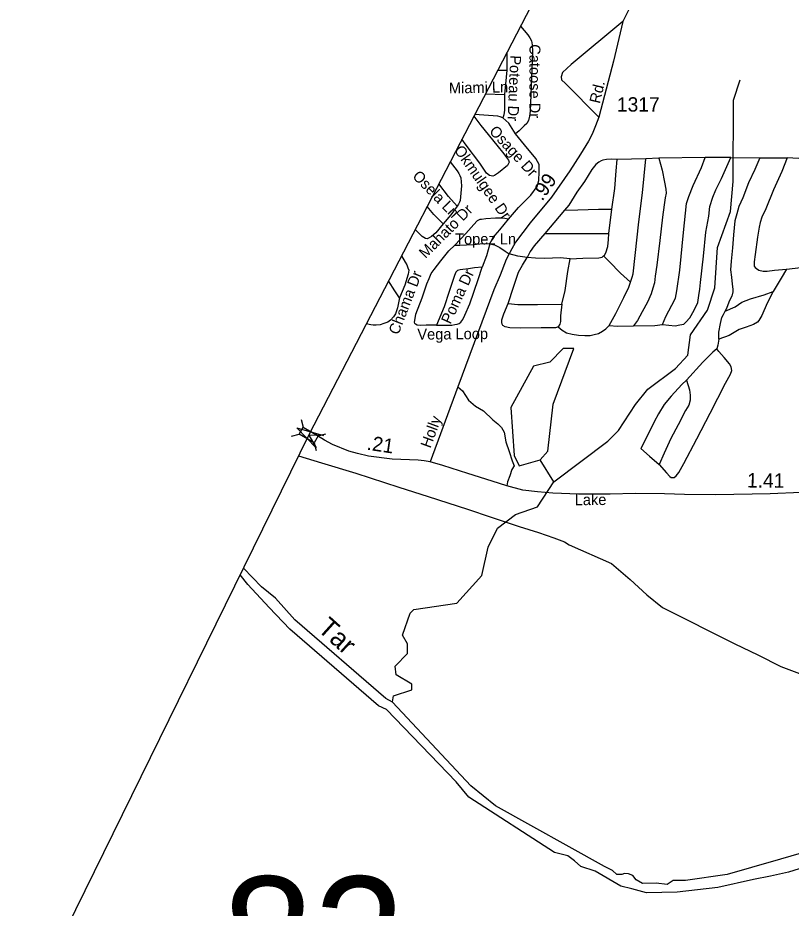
# Model space of a CAD drawing. Extents: x 2220236 to 2384410, y 720751 to 894131.
# Drawn here: x 2239554 to 2246280, y 793475 to 801219 of the extents above; entities that cross this region are included whole.
import ezdxf

# ---------------------------------------------------------------- set-up
doc = ezdxf.new("R2010")
doc.units = 0
for name, color, linetype in [('Exist Boundary Political CountyLine', 7, 'Continuous'), ('Exist Hydrographic Misc Water Feature', 7, 'Continuous'), ('Exist Hydrographic Pond Under 1500 Sq Ft', 7, 'Continuous'), ('Exist Hydrographic River Shore', 7, 'Continuous'), ('Exist Hydrographic River Shore Label', 7, 'Continuous'), ('Exist Railroad Mainline', 7, 'Continuous'), ('Exist Road Non-System Type 51', 7, 'Continuous'), ('Exist Road Non-System Type 51 Label', 7, 'Continuous'), ('Exist Road Secondary Mileage Hundredths English Label', 7, 'Continuous'), ('Exist Road Secondary Structure Standard Bridge Attributed CELL', 7, 'Continuous'), ('Exist Road Secondary Structure Standard Bridge CELL', 7, 'Continuous'), ('Exist Road Secondary Structure Standard Bridge Number Label', 7, 'Continuous'), ('Exist Road Secondary Type 51 Attributed', 7, 'Continuous'), ('Exist Road Secondary Type 51 Label', 7, 'Continuous'), ('Exist Road Secondary Type 51 Number Label', 7, 'Continuous')]:
    doc.layers.add(name, color=color, linetype=linetype)

msp = doc.modelspace()

# ---------------------------------------------------------------- linework, layer by layer
at = {"layer": 'Exist Boundary Political CountyLine'}
msp.add_lwpolyline([(2293117.8, 894131.3), (2291903.9, 891776.4), (2258821.6, 829664.6), (2255410.5, 823324), (2242088.6, 797598.7), (2231459.6, 775980.5), (2225010.8, 762953.2), (2220575.6, 753519.5)], dxfattribs=at)
at = {"layer": 'Exist Hydrographic Misc Water Feature'}
msp.add_line((2244214.5, 797182.9), (2244096.6, 797375.5), dxfattribs=at)
for points in [[(2244214.5, 797182.9), (2244686.6, 797537.2), (2244777.6, 797630.4), (2244925.7, 797857), (2245032.7, 797989.3), (2245272.6, 798168), (2245380.7, 798283.8), (2245403.6, 798460.5), (2245551.7, 798677.2), (2245616.7, 798869.4), (2245639.7, 799219.9), (2245752.7, 799535.7), (2245775.6, 799794.4), (2245778.7, 800502.8), (2245835.7, 800678.7)], [(2242812.8, 795268.5), (2242821.6, 795322.3), (2242979.7, 795374.8), (2242979.7, 795423.9), (2242845.6, 795505.4), (2242836.6, 795581), (2242943.6, 795690.4), (2242943.6, 795775.6), (2242900.5, 795848.7), (2242966.6, 796040.9), (2242999.6, 796073), (2243373.6, 796127.6), (2243588.7, 796369.2), (2243644.7, 796614), (2243726.7, 796779.6), (2243883.6, 796897.7), (2244074.7, 796966), (2244214.5, 797182.9)]]:
    msp.add_lwpolyline(points, dxfattribs=at)
at = {"layer": 'Exist Hydrographic Pond Under 1500 Sq Ft'}
msp.add_lwpolyline([(2244096.6, 797375.5), (2244162.7, 797449.6), (2244209.6, 797858.6), (2244388.6, 798343.7), (2244296.6, 798342.3), (2244181.7, 798223.3), (2244039.6, 798190.1), (2243842.6, 797830.1), (2243871.7, 797413), (2243913.7, 797323.5), (2244096.6, 797375.5)], dxfattribs=at)
at = {"layer": 'Exist Hydrographic River Shore'}
for points in [[(2242813.9, 795268), (2242753.7, 795297.4), (2241964.8, 795982.4), (2241793.9, 796172.1), (2241673.7, 796271.2), (2241515.8, 796433.6)], [(2242761, 795202.9), (2242692.2, 795234.1), (2241918.9, 795901.1), (2241739.7, 796090.8), (2241554.2, 796290.9), (2241486.9, 796374.9)], [(2246457.5, 793979.4), (2246186.6, 793902.1), (2245934.4, 793829.6), (2245721.7, 793768.9), (2245361.1, 793716.8), (2245254.8, 793714.7), (2245200.7, 793681.3), (2245106.9, 793693.8), (2244987, 793689.7), (2244932.8, 793723), (2244903.6, 793760.5), (2244864, 793775.1), (2244830.7, 793777.2), (2244805.7, 793768.9), (2244764, 793766.8), (2244726.5, 793804.3), (2244655.6, 793837.7), (2243709.9, 794365.8), (2243493.9, 794539.6), (2242813.9, 795268)], [(2248133.3, 794333.7), (2247487.2, 794296), (2247206.4, 794232.9), (2246432.5, 793843.9), (2246257.4, 793787.6), (2246100, 793754.3), (2245952, 793725.1), (2245641.5, 793654.2), (2245287.2, 793614.6), (2245020.4, 793608.4), (2244895.3, 793643.8), (2244797.3, 793666.7), (2244576.4, 793796), (2244449.3, 793837.7), (2244395.1, 793885.6), (2244338.8, 793931.5), (2244222.1, 793960.6), (2243475.9, 794442.1), (2243365.4, 794573.4), (2242761, 795202.9)]]:
    msp.add_lwpolyline(points, dxfattribs=at)
at = {"layer": 'Exist Railroad Mainline'}
msp.add_lwpolyline([(2241996.1, 797410.4), (2242194.8, 797349), (2242493.3, 797259.4), (2242868.3, 797136.7), (2243122.7, 797056.7), (2243463.6, 796945.4), (2243671.9, 796877.1), (2243914.6, 796795.2), (2244082.9, 796742.7), (2244215.3, 796695.8), (2244309.6, 796662.4), (2244349.8, 796634.8), (2244716.1, 796474.3), (2244878.6, 796332.6), (2245024.5, 796199.2), (2245162.1, 796090.8), (2245789.5, 795774), (2245989.6, 795678.1), (2246189.7, 795578.1), (2246375.2, 795507.2)], dxfattribs=at)
at = {"layer": 'Exist Road Non-System Type 51'}
for p, q in [((2243728, 800764.5), (2243807.9, 800762.9)), ((2243807.9, 800762.9), (2243787.9, 800552.8)), ((2243621.4, 800558.6), (2243787.9, 800552.8)), ((2245015.6, 799992.7), (2244765.9, 799985.5)), ((2245129.2, 799996.9), (2245015.6, 799992.7)), ((2245531.6, 800005.1), (2245129.2, 799996.9)), ((2245754.5, 800003), (2245531.6, 800005.1)), ((2245754.5, 800003), (2246008.3, 800002)), ((2244693.7, 799342.2), (2244720.5, 799553.9)), ((2246239.5, 799033.5), (2246363.3, 799047.9))]:
    msp.add_line(p, q, dxfattribs=at)
for points in [[(2243925.9, 801146.6), (2243988.5, 801071), (2244008.2, 801044.7), (2244020.1, 801018.4), (2244026.6, 800984.2), (2244029.3, 800924.9), (2244016.1, 800549.9), (2244010.8, 800407.8), (2244003, 800363.1), (2243994.4, 800326.9), (2243979.9, 800300.6), (2243958.9, 800278.2), (2243914.1, 800234.8), (2243881.2, 800211.1)], [(2244815.9, 801186.1), (2244366, 800811.5), (2244291.6, 800743.2), (2244279.2, 800706), (2244281.1, 800681), (2244316.3, 800647.9), (2244606, 800354.1)], [(2243806, 800915), (2243807.7, 800848), (2243807.9, 800762.9)], [(2243787.9, 800552.8), (2243785.8, 800416.2), (2243781.7, 800374.8), (2243773.4, 800350)], [(2243520.3, 800363.3), (2243580.4, 800281.9), (2243719.4, 800112.4), (2243780.5, 800035.7), (2243804.5, 800005.1), (2243822.5, 799979.9), (2243826, 799963.7), (2243812.9, 799935.6), (2243734, 799871.9), (2243698.9, 799847.1), (2243684.5, 799843), (2243655.6, 799847.1), (2243630.8, 799867.8), (2243571.4, 799953.6), (2243453.9, 800112.4), (2243416.7, 800163.3)], [(2243773.4, 800350), (2243749.9, 800359.2), (2243727.8, 800364.6), (2243527.2, 800376.7)], [(2243881.2, 800211.1), (2243824.7, 800303.2), (2243773.4, 800350)], [(2243822.8, 799468.2), (2243909.4, 799570.4), (2244016.8, 799675.6), (2244070.7, 799751.9), (2244084.5, 799803.9), (2244088.5, 799878.9), (2244087.2, 799943.3), (2244074, 799969.7), (2244059.5, 799994.7), (2243960.2, 800113.7), (2243881.2, 800211.1)], [(2243315.5, 799967.8), (2243375.7, 799887.3), (2243389.8, 799864.3), (2243399.4, 799847.5), (2243407.8, 799827.1), (2243412.6, 799758.8), (2243402.7, 799662.6), (2243400, 799630.6), (2243394.6, 799616.2), (2243385.6, 799598.2), (2243374.8, 799582)], [(2244765.9, 799985.5), (2244714.3, 799989.6), (2244673.1, 799985.5), (2244642.1, 799981.4), (2244627.6, 799975.2), (2244607, 799964.8), (2244582.2, 799944.2), (2244545.1, 799898.8), (2244483.2, 799795.5), (2244415.1, 799702.6), (2244344.9, 799589), (2244309.8, 799545.6)], [(2244720.5, 799553.9), (2244747.3, 799734.6), (2244757.7, 799889.5), (2244765.9, 799985.5)], [(2244881.5, 798920.9), (2244897.5, 798964.4), (2244905.7, 798993.4), (2244922.8, 799152.2), (2244953.7, 799445.5), (2244986.8, 799697.4), (2245015.6, 799992.7)], [(2245129.2, 799996.9), (2245158, 799894.6), (2245178.7, 799789.3), (2245191.1, 799729.4), (2245193.1, 799694.3), (2245184.9, 799653), (2245176.6, 799591.1), (2245160.1, 799485.7), (2245137.4, 799283.3), (2245110.6, 799068.6), (2245098.2, 798971.5), (2245089.9, 798912.7), (2245077.6, 798867.2), (2245061, 798819.7), (2245030.1, 798745.4), (2244982.6, 798660.7), (2244943.4, 798586.4), (2244908.3, 798539.9)], [(2245160.1, 798550.2), (2245191.1, 798621.5), (2245240.6, 798718.5), (2245273.6, 798780.5), (2245286, 798844.5), (2245312.8, 799024.2), (2245343.8, 799350.5), (2245370.6, 799604.5), (2245389.2, 799665.4), (2245426.3, 799760.4), (2245498.6, 799917.3), (2245531.6, 800005.1)], [(2245160.1, 798550.2), (2245269.5, 798539.9), (2245310.8, 798548.2), (2245345.9, 798554.4), (2245364.4, 798570.9), (2245399.5, 798610.1), (2245436.7, 798676.2), (2245467.6, 798742.3), (2245477.9, 798804.2), (2245484.1, 798857.9), (2245490.3, 798917.8), (2245517.2, 799145), (2245537.8, 799353.6), (2245562.6, 799494), (2245572.9, 799578.7), (2245597.6, 799658.2), (2245624.5, 799723.2), (2245674, 799821.3), (2245754.5, 800003)], [(2246008.3, 800002), (2245962.9, 799900.8), (2245909.3, 799783.1), (2245859.7, 799653), (2245824.7, 799578.7), (2245806.1, 799514.6), (2245789.6, 799452.7), (2245779.3, 799332.9), (2245768.9, 799217.3), (2245758.6, 799103.7), (2245752.4, 799027.3), (2245760.7, 798963.3), (2245766.9, 798903.4), (2245773.1, 798857.9), (2245771, 798835.2), (2245762.7, 798798), (2245744.2, 798760.9), (2245719.4, 798698.9), (2245707, 798667.9)], [(2246245.7, 800002), (2246198.2, 799883.3), (2246126, 799724.3), (2246057.9, 799559), (2246024.9, 799484.7), (2246010.4, 799439.3), (2246002.2, 799398), (2245987.7, 799310.2), (2245967.1, 799159.4), (2245958.8, 799097.5), (2245956.7, 799058.2), (2245967.1, 799047.9), (2245979.4, 799037.6), (2245998, 799025.2), (2246035.2, 799014.9), (2246072.3, 799014.9), (2246134.2, 799025.2), (2246239.5, 799033.5)], [(2246008.3, 800002), (2246194.1, 800002), (2246245.7, 800002)], [(2246390.1, 799998.9), (2246346.8, 799994.8), (2246293.1, 799996.9), (2246245.7, 800002)], [(2243374.8, 799582), (2243300.8, 799664.4), (2243215.2, 799774.1)], [(2243252, 799427.4), (2243172.9, 799507.1), (2243113.6, 799578)], [(2243374.8, 799582), (2243319.1, 799504.1), (2243252, 799427.4)], [(2244309.8, 799545.6), (2244216.9, 799435.1), (2244136.5, 799344.3)], [(2244309.8, 799545.6), (2244425.4, 799549.8), (2244602.9, 799553.9), (2244720.5, 799553.9)], [(2243252, 799427.4), (2243188.7, 799349.8), (2243151.6, 799318), (2243131.2, 799304.9), (2243114.4, 799295.9), (2243098.3, 799298.3), (2243071.3, 799316.8), (2243009.9, 799377.7)], [(2243822.8, 799468.2), (2243771.2, 799476.4), (2243707.2, 799476.4), (2243624.6, 799470.2), (2243587.5, 799466.1), (2243571, 799464), (2243550.3, 799453.7), (2243519.4, 799420.7), (2243451.3, 799342.2), (2243354.3, 799241)], [(2243659.7, 799253.4), (2243686.5, 799305), (2243746.4, 799375.2), (2243822.8, 799468.2)], [(2244136.5, 799344.3), (2244045.6, 799234.8), (2244008.5, 799185.3), (2243983.7, 799135.7)], [(2244136.5, 799344.3), (2244342.8, 799344.3), (2244693.7, 799342.2)], [(2244649, 799147.6), (2244652.4, 799150.1), (2244668.9, 799174.9), (2244685.4, 799230.7), (2244691.6, 799290.6), (2244693.7, 799342.2)], [(2243354.3, 799241), (2243399.7, 799241), (2243515.2, 799247.2), (2243601.9, 799257.5), (2243659.7, 799253.4)], [(2243195.4, 798547.1), (2243106.6, 798545.1), (2243053, 798543), (2243026.1, 798547.1), (2243013.7, 798553.3), (2243007.5, 798561.6), (2243005.5, 798571.9), (2243007.5, 798586.4), (2243015.8, 798642.1), (2243069.5, 798782.6), (2243110.7, 798904.4), (2243131.4, 798951.9), (2243150, 798995.3), (2243174.7, 799030.4), (2243232.5, 799104.7), (2243302.7, 799193.5), (2243354.3, 799241)], [(2243659.7, 799253.4), (2243628.8, 799150.1), (2243593.7, 799051)], [(2243659.7, 799253.4), (2243701, 799243.1), (2243746.4, 799220.4), (2243791.8, 799189.4), (2243826.5, 799165.5)], [(2242891, 799148), (2242924.2, 799093.4), (2242937.3, 799071.6), (2242947.4, 799045.5), (2242954, 799024.4), (2242949.6, 798990.3), (2242919.8, 798893.7), (2242873, 798782.2)], [(2243818.6, 798733), (2243864, 798877.5), (2243909.4, 799005.6), (2243944.5, 799067.5), (2243983.7, 799135.7)], [(2243983.7, 799135.7), (2243903.2, 799146), (2243826.5, 799165.5)], [(2244357.3, 799123.3), (2244270.6, 799131.6), (2244138.5, 799125.4), (2244056, 799127.4), (2243983.7, 799135.7)], [(2244285.1, 798728.9), (2244313.9, 798848.6), (2244338.7, 799013.8), (2244357.3, 799123.3)], [(2244357.3, 799123.3), (2244466.7, 799129.5), (2244607, 799131.6), (2244635.9, 799137.8), (2244649, 799147.6)], [(2244881.5, 798920.9), (2244794.8, 798997.3), (2244695.8, 799098.5), (2244649, 799147.6)], [(2243593.7, 799051), (2243525.6, 799044.8), (2243474, 799036.6), (2243424.4, 799030.4), (2243401.7, 799028.3), (2243379, 799020), (2243364.6, 799005.6), (2243352.2, 798976.7), (2243306.8, 798838.3), (2243261.4, 798706.1), (2243195.4, 798547.1)], [(2243195.4, 798547.1), (2243267.6, 798547.1), (2243327.4, 798547.1), (2243354.3, 798551.3), (2243374.9, 798555.4), (2243391.4, 798561.6), (2243405.9, 798571.9), (2243424.4, 798594.6), (2243443, 798631.8), (2243484.3, 798730.9), (2243556.5, 798941.6), (2243593.7, 799051)], [(2246239.5, 799033.5), (2246192, 798955), (2246123.9, 798837.3)], [(2242873, 798782.2), (2242833, 798843.9), (2242778.7, 798931.3)], [(2244697.8, 798542), (2244753.5, 798648.3), (2244823.7, 798786.7), (2244867, 798875.5), (2244881.5, 798920.9)], [(2246123.9, 798837.3), (2246072.3, 798736.1), (2246024.9, 798630.8), (2245998, 798587.4), (2245985.6, 798572.9), (2245950.6, 798550.2), (2245888.6, 798529.6), (2245828.8, 798506.9), (2245740, 798455.2), (2245649.2, 798424.2)], [(2245707, 798667.9), (2245793.7, 798705.1), (2245851.5, 798746.4), (2245925.8, 798775.3), (2246045.5, 798810.4), (2246123.9, 798837.3)], [(2242873, 798782.2), (2242854.8, 798697.9), (2242838.1, 798644.1), (2242820.7, 798619.5), (2242796, 798589.7), (2242772, 798572.2), (2242736.8, 798559.5), (2242706.3, 798550.1), (2242672.1, 798546.5), (2242644.5, 798547.2), (2242624.2, 798547.9), (2242585.2, 798557.6)], [(2244254.1, 798532.7), (2244229.3, 798522.3), (2244204.6, 798522.3), (2244105.5, 798522.3), (2243921.8, 798520.3), (2243833.1, 798522.3), (2243793.9, 798530.6), (2243771.2, 798543), (2243765, 798555.4), (2243762.9, 798567.8), (2243762.9, 798592.6), (2243781.5, 798644.2), (2243818.6, 798733)], [(2243818.6, 798733), (2243903.2, 798724.7), (2244072.5, 798724.7), (2244285.1, 798728.9)], [(2244285.1, 798728.9), (2244272.7, 798625.6), (2244272.7, 798578.1), (2244266.5, 798555.4), (2244254.1, 798532.7)], [(2245649.2, 798424.2), (2245651.3, 798486.2), (2245663.7, 798560.5), (2245677.3, 798613.5), (2245690.5, 798638), (2245707, 798667.9)], [(2244254.1, 798532.7), (2244287.1, 798502.7), (2244326.3, 798477.9), (2244373.8, 798467.6), (2244429.5, 798459.4), (2244485.2, 798455.2), (2244532.7, 798457.3), (2244565.7, 798463.5), (2244604.9, 798473.8), (2244638, 798492.4), (2244668.9, 798515.1), (2244697.8, 798542)], [(2244697.8, 798542), (2244770, 798537.8), (2244908.3, 798539.9)], [(2244908.3, 798539.9), (2245094.1, 798544), (2245160.1, 798550.2)], [(2245649.2, 798424.2), (2245641, 798372.6), (2245632.7, 798339.6)], [(2245130.7, 797333.2), (2245194.7, 797260.9), (2245223.6, 797230), (2245236, 797221.7), (2245248.3, 797221.7), (2245262.8, 797221.7), (2245279.3, 797236.2), (2245304.1, 797265.1), (2245345.3, 797343.5), (2245458.9, 797556.2), (2245574.4, 797779.3), (2245708.6, 798041.6), (2245751.9, 798121.1), (2245764.3, 798152), (2245758.1, 798183), (2245743.7, 798209.9), (2245696.2, 798265.6), (2245650.8, 798317.3), (2245632.7, 798339.6)], [(2245632.7, 798339.6), (2245599.2, 798311.1), (2245512.5, 798224.3), (2245370.1, 798067.4)], [(2245370.1, 798067.4), (2245328.8, 798029.2), (2245236, 797928), (2245176.1, 797855.7), (2245124.5, 797775.2), (2245089.4, 797704.9), (2245035.8, 797597.6), (2244971.8, 797473.6), (2245048.2, 797405.5), (2245130.7, 797333.2)], [(2245370.1, 798067.4), (2245394.9, 797984.8), (2245401.1, 797937.3), (2245401.1, 797893.9), (2245388.7, 797850.5), (2245361.9, 797803), (2245295.8, 797679.1), (2245233.9, 797559.3), (2245174, 797432.3), (2245130.7, 797333.2)], [(2243380.1, 798008.1), (2243420.3, 797974), (2243472.9, 797893.5), (2243534.9, 797840.8), (2243603, 797800.6), (2243686.5, 797723.1), (2243729.9, 797689.1), (2243760.8, 797655), (2243782.5, 797614.7), (2243798, 797531.1), (2243825.9, 797447.4), (2243853.7, 797366.9), (2243870.2, 797322.5), (2243850.6, 797289.5), (2243832, 797236.8), (2243813.5, 797184.1), (2243806.2, 797147)]]:
    msp.add_lwpolyline(points, dxfattribs=at)
at = {"layer": 'Exist Road Secondary Structure Standard Bridge Attributed CELL'}
msp.add_lwpolyline([(2242149.1, 797477.5), (2241979.7, 797653), (2242214.1, 797585.7), (2242084.2, 797590.2)], close=True, dxfattribs=at)
at = {"layer": 'Exist Road Secondary Structure Standard Bridge CELL'}
for p, q in [((2242019.3, 797726.8), (2242036.6, 797660)), ((2241934.1, 797581.8), (2242000.9, 797599.2)), ((2242166.7, 797583.1), (2242233.5, 797600.5)), ((2242131.8, 797523.7), (2242149.1, 797456.9))]:
    msp.add_line(p, q, dxfattribs=at)
msp.add_lwpolyline([(2242036.6, 797660), (2242166.9, 797583.4), (2242131.1, 797522.6), (2242000.9, 797599.2)], close=True, dxfattribs=at)
at = {"layer": 'Exist Road Secondary Type 51 Attributed'}
for points in [[(2244874.9, 801304.1), (2244815.9, 801186.1), (2244734.2, 800842.6), (2244657.7, 800544.5), (2244606, 800354.1), (2244578, 800279.6), (2244549.1, 800207.2), (2244518.1, 800145.1), (2244448.1, 800034), (2244355.2, 799889.5), (2244196.3, 799660.2), (2244008.5, 799437.2), (2243881.8, 799266.5), (2243833.4, 799178.5), (2243826.5, 799165.5), (2243800.9, 799117), (2243749.2, 798980), (2243692.7, 798851.7), (2243380.1, 798008.1), (2243141.7, 797356.9)], [(2243141.7, 797356.9), (2243088.3, 797365.6), (2243036, 797371.9), (2242961.9, 797374.6), (2242811.2, 797381.8), (2242605.5, 797406.6), (2242509.3, 797430), (2242434.1, 797451), (2242291.7, 797508.3), (2242221.4, 797546.6), (2242100.7, 797622)], [(2246366.9, 797090.6), (2246096.6, 797078.2), (2245624, 797068.9), (2245351.5, 797073), (2245178.2, 797079.2), (2244924.3, 797081.3), (2244705.6, 797077.1), (2244431.1, 797077.1), (2244208.2, 797085.4), (2244074.5, 797095.3), (2243946.6, 797109.8), (2243806.2, 797147), (2243678.3, 797188.3), (2243467.8, 797254.3), (2243251.1, 797326.6), (2243141.7, 797356.9)]]:
    msp.add_lwpolyline(points, dxfattribs=at)

# ---------------------------------------------------------------- texts
at = {"layer": 'Exist Hydrographic River Shore Label'}
msp.add_text('Tar', height=167.32, rotation=317.96069, dxfattribs=at).set_placement((2242152.4, 795894.8))
at = {"layer": 'Exist Road Non-System Type 51 Label'}
for s, rotation, p in [('Catoose Dr', 269.99404, (2244003.8, 800989.1)), ('Poteau Dr', 267.60382, (2243837.1, 800894.5)), ('Miami Ln', 1.0942, (2243304.2, 800560.7)), ('Osage Dr', 312.40684, (2243647.6, 800228)), ('Okmulgee Dr', 305.01308, (2243344.1, 800068.3)), ('Osela Ln', 314.15579, (2242979.9, 799835.4)), ('Mahato Dr', 45.01382, (2243099.8, 799120.3)), ('Poma Dr', 65.28556, (2243317, 798548.4)), ('Chama Dr', 68.77747, (2242863.3, 798455.9)), ('Vega Loop', 0.51514, (2243029.2, 798419.5))]:
    msp.add_text(s, height=95, rotation=rotation, dxfattribs=at).set_placement(p)
msp.add_text('Topez Ln', height=95, dxfattribs=at).set_placement((2243357.4, 799248.2))
at = {"layer": 'Exist Road Secondary Mileage Hundredths English Label'}
for s, rotation, p in [('.99', 55.18216, (2244114.4, 799619)), ('.21', 351.59194, (2242584.4, 797463.2)), ('1.41', 359.49428, (2245894.9, 797134.2))]:
    msp.add_text(s, height=125, rotation=rotation, dxfattribs=at).set_placement(p)
at = {"layer": 'Exist Road Secondary Structure Standard Bridge Number Label'}
msp.add_text('82', height=1066.27, dxfattribs=at).set_placement((2241332.5, 792684.1))
at = {"layer": 'Exist Road Secondary Type 51 Label'}
for s, rotation, p in [('Rd.', 76.66818, (2244615.8, 800468)), ('Holly', 69.81002, (2243141.9, 797470.2)), ('Lake', 0.46531, (2244397.6, 796979.6))]:
    msp.add_text(s, height=95, rotation=rotation, dxfattribs=at).set_placement(p)
at = {"layer": 'Exist Road Secondary Type 51 Number Label'}
msp.add_text('1317', height=125, dxfattribs=at).set_placement((2244764.4, 800403.4))

doc.saveas('drawing.dxf')
